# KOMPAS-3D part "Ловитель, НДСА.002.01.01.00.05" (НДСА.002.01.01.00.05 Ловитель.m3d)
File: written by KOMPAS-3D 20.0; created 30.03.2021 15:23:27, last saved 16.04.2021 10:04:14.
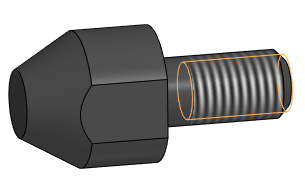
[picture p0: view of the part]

Document properties: Автор: 111; Полное имя файла: C:\Users\korychko\Desktop\PLM\НДСА.002.01.01.00.05 Ловитель.m3d

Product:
- Part/product: Ловитель  | designation НДСА.002.01.01.00.05
    Масса: 0.0514597
    additional columns: <item xmlns="http://appius.ru/pdm" xmlns:xs="http://www.w3.org/2001/XMLSchema" x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; <item xmlns="http://appius.ru/pdm" xmlns:xs="http://www.w3.org/2001/XMLSchema" x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; <item xmlns="http://appius.ru/pdm" xmlns:xs="http://www.w3.org/2001/XMLSchema" x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
    source file: НДСА.002.01.01.00.05 Ловитель.cdw

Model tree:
1. Эскиз:1
2. Элемент выдавливания:1
     Расстояние 1 = 20
3. Эскиз:2  (with: Элемент выдавливания:1)
4. Элемент выдавливания:2
     Расстояние 1 = 20
5. Фаска:1  (with: Элемент выдавливания:1)
     Угол = 60; Длина 1 = 5; Длина 2 = 8.66025
6. Условное изображение резьбы:2  (with: Элемент выдавливания:2)  (labels: cil0_24705-2004 coarse; M10)
     Длина резьбы = 15; Шаг резьбы = 1.5; Номинальный диаметр резьбы = 10
7. Подгонка:2  (with: Элемент выдавливания:2)
8. Фаска:2  (with: Элемент выдавливания:2)
     Угол = 45; Длина 1 = 1.5; Длина 2 = 1.5
9. Эскиз:5  (with: Элемент выдавливания:1)
10. Элемент выдавливания:3
     Расстояние 2 = 20

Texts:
  НДСА.002.01.01.00.05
